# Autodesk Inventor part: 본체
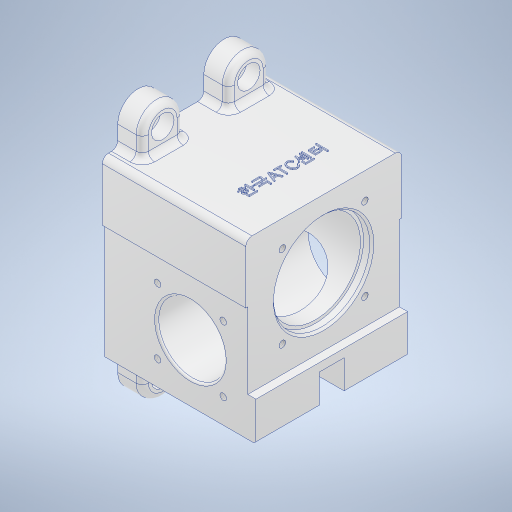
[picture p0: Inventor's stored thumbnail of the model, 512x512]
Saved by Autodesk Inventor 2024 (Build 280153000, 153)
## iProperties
Created: 2024-11
Part Number: 본체
Material: 알루미늄 6061
Document SubType Name: Modeling
Designer: user
Density: 2.7 g/cm^3
Appearance: 알루미늄 - 평지
Mass: 820.853 g
Surface Area: 546.228 cm^2
Volume: 304.02 cm^3
Author: user
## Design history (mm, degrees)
sketch "스케치1"
  geometry: L1 (-37, 0)-(37, 0); L2 (-37, 0)-(-37, 85); L3 (-37, 85)-(33, 85); L4 (33, 85)-(33, 19); L5 (33, 19)-(37, 19); L6 (37, 19)-(37, 0); L7 (-37, 56)-(33, 56); 2 further points
  constraints: 14 end point, 3 horizontal, 2 point on line, 1 coincident, 1 midpoint, 1 parallel, 1 perpendicular, 1 vertical
  dimensions: "d0" = 74 distance of L1.start L1.end; "d5" = 85 distance of L1.start L2.end; "d7" = 70 distance of L2.end L3.end; "d8" = 66 distance of L3.end L4.end; "d9" = 4 distance of L4.end L5.end; "d10" = 56 distance between parallel lines of L1 L7
extrude "돌출1" new body sketch "스케치1" stored distance "d11" = 74; taper "d12" = 0 deg
extrude "돌출2" join sketch "스케치1" stored distance "d13" = 76; taper "d14" = 0 deg
sketch "스케치2"
  geometry: L1 (-37, 56)-(-37, 0) reference; L2 (33, 85)-(-37, 85) reference; C1 r 16.5 at (5, 28); 1 further point
  constraints: 1 centre point
  dimensions: "d15" = 33 diameter of C1; "d16" = 57 distance from line of L2 C1.centre; "d17" = 42 distance from line of C1.centre L1
extrude "돌출3" cut sketch "스케치2" distance "d18" = 76; taper "d19" = 0 deg
fillet "모깎기1" dims "d20" = 1
sketch "스케치3"
  geometry: C1 r 17.5 at (5, 28) reference; 5 further points
  constraints: 2 horizontal alignment, 2 vertical alignment
  dimensions: "d21" = 32 distance of point (21, 12) point (-11, 12); "d22" = 16 horizontal distance of C1.centre point (21, 12); "d23" = 32 distance of point (-11, 12) point (-11, 44); "d24" = 16 horizontal distance of C1.centre point (-11, 12)
hole "구멍1" sketch "스케치3" at (-11, 44), (21, 44), (21, 12), (-11, 12) diameter "d25" = 3.242; stored, may be unused: countersink angle "d29" = 90 deg, drill point angle "d31" = 118 deg; dims "d26" = 8, "d27" = 4, "d28" = 2, "d30" = 10
sketch "스케치4"
  geometry: L1 (0, 0)-(74, 0) reference; L2 (31, 15)-(43, 15); L3 (43, 15)-(43, 0); L4 (43, 0)-(31, 0); L5 (31, 0)-(31, 15); 3 further points
  constraints: 8 end point, 2 midpoint, 2 parallel, 1 horizontal, 1 perpendicular, 1 point on line
  dimensions: "d32" = 12 distance of L3.end L4.end; "d33" = 15 distance of L2.end L3.end
extrude "돌출4" cut sketch "스케치4" extent not by distance; stored distance "d34" = 0; taper "d35" = 0 deg
sketch "스케치5"
  geometry: L1 (-31, 0)-(0, 0) reference; L2 (1, 85)-(-75, 85) reference; L3 (-74, 0)-(-43, 0) reference; L4 (-68.5, 95)-(-68.5, 85); L5 (-48.5, 95)-(-48.5, 85); L6 (-6.5, 95)-(-6.5, 85); L7 (-26.5, 95)-(-26.5, 85); L8 (-68.5, -10)-(-68.5, 0); L9 (-48.5, -10)-(-48.5, 0); L10 (-26.5, -10)-(-26.5, 0); L11 (-6.5, -10)-(-6.5, 0); A1 r 10 centre (-58.5, 95) between (-48.5, 95) and (-68.5, 95); A2 r 10 centre (-16.5, 95) between (-6.5, 95) and (-26.5, 95); A3 r 10 centre (-58.5, -10) between (-68.5, -10) and (-48.5, -10); A4 r 10 centre (-16.5, -10) between (-26.5, -10) and (-6.5, -10); 3 further points
  constraints: 16 end point, 10 point on circle, 8 point on line, 6 perpendicular, 4 centre point, 4 tangent, 1 parallel, 1 vertical
  dimensions: "d37" = 20 diameter of A1; "d38" = 10 vertical distance of A1.centre L2.end; "d39" = 20 diameter of A2; "d40" = 10 distance from line of A2.centre L2; "d41" = 42 distance of A2.centre A1.centre; "d42" = 20 diameter of A3; "d43" = 20 diameter of A4; "d44" = 42 distance of A4.centre A3.centre; "d45" = 10 distance from line of A3.centre L3; "d46" = 10 distance from line of L1 A4.centre; "d47" = 125 distance of point (-58.5, -20) point (-58.5, 105); "d48" = 22 distance of L7.end L5.end; "d49" = 6.5 distance of L2.end L4.end; "d50" = 7.5 distance of L2.start L6.end; "d51" = 5.5 distance of L3.start L8.end; "d52" = 22 distance of L10.end L9.end
extrude "돌출5" join sketch "스케치5" distance "d53" = 12; taper "d54" = 0 deg
sketch "스케치6"
  geometry: A1 r 10 centre (16.5, 95) between (26.5, 95) and (6.5, 95) reference; A2 r 10 centre (58.5, 95) between (68.5, 95) and (48.5, 95) reference; A3 r 10 centre (16.5, -10) between (6.5, -10) and (26.5, -10) reference; A4 r 10 centre (58.5, -10) between (48.5, -10) and (68.5, -10) reference; 5 further points
  constraints: 4 coincident
hole "구멍2" sketch "스케치6" at (16.5, 95), (58.5, 95), (58.5, -10), (16.5, -10) diameter "d55" = 6.6; stored, may be unused: countersink angle "d59" = 90 deg, drill point angle "d61" = 118 deg; dims "d56" = 8, "d57" = 11, "d58" = 6.6, "d60" = 6.6
sketch "스케치7"
  geometry: L1 (75, 66)-(-1, 66) reference; C1 r 23.5 at (37, 33); 2 further points
  constraints: 1 centre point, 1 midpoint, 1 vertical alignment
  dimensions: "d62" = 47 diameter of C1; "d63" = 33 distance of point (37, 66) C1.centre
extrude "돌출6" cut sketch "스케치7" distance "d64" = 4; taper "d65" = 0 deg
sketch "스케치8"
  geometry: C1 r 23.5 at (0, 0) reference; C2 r 22 at (0, 0); 1 further point
  constraints: 1 centre point, 1 coincident
  dimensions: "d66" = 44 diameter of C2
extrude "돌출7" cut sketch "스케치8" distance "d67" = 48; taper "d68" = 0 deg
sketch "스케치9"
  geometry: C1 r 22 at (0, 0) reference; C2 r 17.5 at (0, 0); 1 further point
  constraints: 1 centre point, 1 coincident
  dimensions: "d69" = 35 diameter of C2
extrude "돌출8" cut sketch "스케치9" distance "d70" = 11; taper "d71" = 0 deg
sketch "스케치10"
  geometry: C1 r 17.5 at (0, 0) reference; C2 r 15 at (0, 0); 1 further point
  constraints: 1 centre point, 1 coincident
  dimensions: "d72" = 30 diameter of C2
extrude "돌출9" join sketch "스케치10" distance "d73" = 3; taper "d74" = 0 deg
chamfer "모따기1" distance "d75" = 1; stored, may be unused: second distance "d76" = 2, angle "d77" = 45 deg
fillet "모깎기2" dims "d78" = 0.6
fillet "모깎기3" dims "d79" = 3
sketch "스케치11"
  geometry: L1 (8.5, 33)-(65.5, 33); L2 (16.847, 53.153)-(57.153, 12.847); L3 (16.847, 12.847)-(57.153, 53.153); C1 r 15 at (37, 33) reference; A1 r 28.5 centre (37, 33) between (57.153, 53.153) and (57.153, 12.847); 3 further points
  constraints: 6 end point, 6 point on circle, 4 midpoint, 1 centre point, 1 coincident, 1 horizontal, 1 horizontal alignment
  dimensions: "d80" = 57 diameter of A1; "d81" = 45 deg angle of L1 L2; "d82" = 45 deg angle of L1 L3
hole "구멍3" sketch "스케치11" at (57.153, 53.153), (57.153, 12.847), (16.847, 12.847), (16.847, 53.153) diameter "d83" = 3.242; stored, may be unused: countersink angle "d87" = 90 deg, drill point angle "d89" = 118 deg; dims "d84" = 8, "d85" = 11, "d86" = 6.6, "d88" = 10
sketch "스케치13"
  geometry: L1 (70, 76)-(70, 0) reference; 2 further points
  constraints: 1 horizontal alignment, 1 other
  dimensions: "d93" = 20 distance from line of L1 point (50, 38)
feature "엠보싱2" sketch "스케치13" dims "d0" = 74, "d5" = 85, "d7" = 70, "d8" = 66, "d9" = 4, "d10" = 56, "d94" = 0.5, "d95" = 0
fillet "모깎기4" dims "d96" = 3
fillet "모깎기5" dims "d97" = 3
chamfer "모따기2" distance "d98" = 1; stored, may be unused: second distance "d99" = 2, angle "d100" = 45 deg
chamfer "모따기3" distance "d101" = 1; stored, may be unused: second distance "d102" = 2, angle "d103" = 45 deg
sketch "스케치14"
  geometry: L1 (74, 12)-(74, 0) reference; 4 further points
  constraints: 2 horizontal alignment, 1 midpoint
  dimensions: "d104" = 12 distance of point (62, 6) point (74, 6); "d105" = 40 distance of point (22, 6) point (62, 6)
hole "구멍4" sketch "스케치14" at (62, 6), (22, 6) diameter "d106" = 3.242; stored, may be unused: countersink angle "d110" = 90 deg, drill point angle "d112" = 118 deg; dims "d107" = 8, "d108" = 4, "d109" = 2, "d111" = 10
sketch "스케치15"
  geometry: 1 further point
sketch "스케치16"
  geometry: 1 further point
sketch "스케치17"
  geometry: C1 r 16.9 at (0, 0) reference; C2 r 15 at (0, 0); 1 further point
  constraints: 1 centre point, 1 coincident
  dimensions: "d113" = 30 diameter of C2
extrude "돌출10" cut sketch "스케치17" distance "d114" = 3; taper "d115" = 0 deg
fillet "모깎기6" dims "d116" = 3
node "솔리드1"
mirror "미러1"
node "작업 평면1"
feature "A9D066F2-1C7D-4E18-AEED-F7BC21143FA4" dims "d55" = 6.6, "d56" = 8, "d57" = 11, "d58" = 6.6, "d59" = 90 deg, "d60" = 6.6, "d61" = 118 deg
